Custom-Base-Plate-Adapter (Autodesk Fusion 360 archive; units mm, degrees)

design "Custom-Base-Plate-Adapter" references "Base"
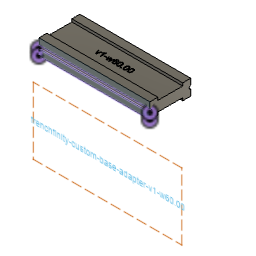
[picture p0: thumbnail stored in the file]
parameter "width" = 60
component_insert "Component Insert"
extrude "Extrude2" new body of existing geometry blind 1
extrude "Extrude1" add of existing geometry blind 59 (= "width - 1 mm")
mirror "Mirror1" mirrorStitchTolerance 0.1
sketch "Filename" plane through (0, 44.7318, 0) normal (0, -1, 0) x axis (1, 0, 0)
  line L1 (40, 50.6559) -> (40, 53.9359)
  line L2 (99, 53.9359) -> (99, 50.6559)
  line L3 (40, 53.9359) -> (99, 53.9359)
  curve K1
  curve K2
  curve K3
  curve K4
  line L4 (99, 50.6559) -> (40, 50.6559)
  line L5 (40, 45.6759) -> (40, 48.9559)
  line L6 (99, 45.6759) -> (40, 45.6759)
  line L7 (99, 48.9559) -> (99, 45.6759)
  line L8 (40, 48.9559) -> (99, 48.9559)
  dimension "d12" Text1-Height = 3
sketch "Name on piece" plane through (0, 0, 52.4859) normal (0, 0, 1) x axis (-1, 0, 0)
  dimension "d13" = 3
extrude "Extrude4" cut sketch "Name on piece" against normal blind 2

design "Base"
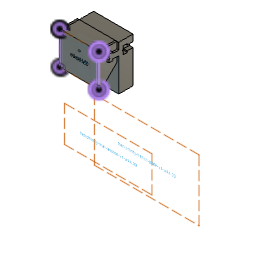
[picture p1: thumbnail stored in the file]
parameter "wall_anchor_height" = 60
parameter "wall_anchor_width" = 20
parameter "wall_anchor_angle" = 45
parameter "width_per_slot" = 40
parameter "slot_inner_width" = 8.5
parameter "slot_inner_height" = 4.5
parameter "slot_outer_width" = 5.6
parameter "slot_outer_height" = 6.5
parameter "slot_dept" = 15
parameter "print_tolerance" = 0.12
parameter "base_plate_thickness" = 16
parameter "base_plate_slot_height" = 50
parameter "wall_anchor_angle_rounded_border" = 1.5
parameter "base_plate_screw_hole_diameter" = 4
parameter "base_plate_screw_head_diameter" = 8
parameter "base_plate_screw_head_height" = 4
parameter "base_plate_screw_hole_side_distance" = 7
parameter "slot_screw_head_width" = 4.42 (= "4.3 mm + print_tolerance")
parameter "slot_screw_thread_width" = 2.12 (= "2 mm + print_tolerance")
parameter "slot_screw_head_height" = 2.12 (= "2 mm + print_tolerance")
parameter "width" = 44
parameter "filament_hole_width" = 1.7
sketch "Side" plane through (0, 0, 0) normal (1, 0, 0) x axis (0, 1, 0)
  line L1 (39.6118, 0) -> (19.6118, 0)
  line L2 (39.6118, 60) -> (39.6118, 0)
  line L3 (19.6118, 60) -> (39.6118, 60)
  line L4 (19.6118, 0) -> (19.6118, 60)
  line L5 (39.6118, 39.6118) -> (0, 0)
  line L6 (56.0196, 0) -> (0, 0)
  point P1 (0, 0)
  point P6 (0, 0)
  point P7 (39.6118, 39.6118)
  point P2 (19.6118, 0)
  point P3 (39.6118, 0)
  point P5 (19.6118, 60)
  horizontal L1
  vertical L2
  horizontal L3
  vertical L4
  horizontal L6
  coincident P1 P6
  coincident L2 P7
  dimension "d4" distance P2 P3 = 20 (= "wall_anchor_width")
  dimension "d5" distance P2 P5 = 60 (= "wall_anchor_height")
  dimension "d6" angle L5 L6 = 45 (= "wall_anchor_angle")
extrude "Extrude1" new body sketch "Side" profile of L1 L2 L3 L4 L5 along normal blind 40 (= "width_per_slot")
sketch "Slot LeftToRight" plane through (0, 0, 0) normal (-1, 0, 0) x axis (0, -1, 0)
  line L1 (-19.6118, 60) -> (-19.6118, 19.6118)
  line L2 (-39.6118, 60) -> (-19.6118, 60)
  line L3 (-39.6118, 39.6118) -> (-39.6118, 60)
  line L4 (-19.6118, 19.6118) -> (-39.6118, 39.6118)
  line L5 (-39.6118, 52.6059) -> (-39.6118, 49.8059)
  line L6 (-39.6118, 47.0059) -> (-39.6118, 49.8059)
  line L7 (-33.1118, 52.6059) -> (-39.6118, 52.6059)
  line L8 (-28.6118, 49.8059) -> (-39.6118, 49.8059)
  line L9 (-28.6118, 54.0559) -> (-28.6118, 49.8059)
  line L10 (-33.1118, 54.0559) -> (-28.6118, 54.0559)
  line L11 (-33.1118, 52.6059) -> (-33.1118, 54.0559)
  line L12 (-28.6118, 45.5559) -> (-28.6118, 49.8059)
  line L13 (-33.1118, 45.5559) -> (-28.6118, 45.5559)
  line L14 (-33.1118, 47.0059) -> (-33.1118, 45.5559)
  line L15 (-33.1118, 47.0059) -> (-39.6118, 47.0059)
  point P6 (-39.6118, 49.8059)
  point P7 (-39.6118, 52.6059)
  point P17 (-39.6118, 47.0059)
  point P9 (-33.1118, 52.6059)
  point P16 (-33.1118, 47.0059)
  point P10 (-28.6118, 49.8059)
  point P13 (-28.6118, 49.8059)
  point P11 (-28.6118, 54.0559)
  point P14 (-28.6118, 45.5559)
  point P12 (-33.1118, 54.0559)
  point P15 (-33.1118, 45.5559)
  midpoint L3 P6
  parallel L3 L5
  parallel L3 L6
  perpendicular L3 L7
  perpendicular L6 L8
  perpendicular L8 L9
  perpendicular L9 L10
  symmetric P7 L8 P17
  symmetric P9 L8 P16
  symmetric P10 L8 P13
  symmetric L8 P11 P14
  symmetric L8 P12 P15
  dimension "d80" distance P6 P7 = 2.8 (= "slot_outer_width / 2")
  dimension "d82" distance P7 P9 = 6.5 (= "slot_outer_height")
  dimension "d84" distance P6 P10 = 11 (= "slot_outer_height + slot_inner_height")
  dimension "d85" distance P10 P11 = 4.25 (= "slot_inner_width / 2")
  dimension "d86" distance P11 P12 = 4.5 (= "slot_inner_height")
extrude "Extrude3" cut sketch "Slot LeftToRight" profile of L3 L5 L6 L7 L9 L10 L11 L12 L13 L14 L15 against normal blind 40 (magnitude of "width_per_slot * -1")
sketch "Plate" plane through (0, 39.6118, 0) normal (0, 1, 0) x axis (-1, 0, 0)
  line L1 (0, 39.6118) -> (-40, 39.6118)
  line L2 (-40, 60) -> (0, 60)
  line L3 (0, 10) -> (0, 60)
  line L4 (-40, 10) -> (-40, 60)
  line L5 (-40, 10) -> (0, 10)
  line L6 (-40, 47.0059) -> (0, 47.0059)
  line L7 (-40, 52.6059) -> (-40, 60)
  line L8 (0, 60) -> (0, 52.6059)
  line L9 (0, 52.6059) -> (-40, 52.6059)
  line L10 (-40, 60) -> (0, 60)
  line L11 (-40, 39.6118) -> (-40, 47.0059)
  line L12 (0, 47.0059) -> (0, 39.6118)
  point P2 (0, 60)
  point P3 (-40, 60)
  point P4 (0, 10)
  point P5 (-40, 10)
  perpendicular L1 L3
  perpendicular L1 L4
  dimension "d36" distance P2 P3 = 40 (= "width_per_slot")
  dimension "d37" distance P2 P4 = 50 (= "base_plate_slot_height")
  dimension "d39" distance P3 P5 = 50 (= "base_plate_slot_height")
extrude "Extrude6" new body sketch "Plate" profile of L1 L2 L3 L4 L5 L6 L7 L8 L9 L10 along normal blind 16 (= "base_plate_thickness") bodies "Base plate with slot"
sketch "Slot" plane through (0, 0, 0) normal (-1, 0, 0) x axis (0, -1, 0)
  line L1 (-19.6118, 60) -> (-19.6118, 19.6118)
  line L2 (-39.6118, 60) -> (-19.6118, 60)
  line L3 (-39.6118, 52.6059) -> (-39.6118, 60)
  line L4 (-33.1118, 52.6059) -> (-39.6118, 52.6059)
  line L5 (-33.1118, 54.0559) -> (-33.1118, 52.6059)
  line L6 (-28.6118, 54.0559) -> (-33.1118, 54.0559)
  line L7 (-28.6118, 45.5559) -> (-28.6118, 54.0559)
  line L8 (-33.1118, 45.5559) -> (-28.6118, 45.5559)
  line L9 (-33.1118, 47.0059) -> (-33.1118, 45.5559)
  line L10 (-39.6118, 47.0059) -> (-33.1118, 47.0059)
  line L11 (-39.6118, 39.6118) -> (-39.6118, 47.0059)
  line L12 (-19.6118, 19.6118) -> (-39.6118, 39.6118)
  line L13 (-33.1118, 52.6059) -> (-39.6118, 52.6059)
  line L14 (-33.1118, 54.0559) -> (-33.1118, 52.6059)
  line L15 (-28.6118, 54.0559) -> (-33.1118, 54.0559)
  line L16 (-28.6118, 45.5559) -> (-28.6118, 54.0559)
  line L17 (-33.1118, 45.5559) -> (-28.6118, 45.5559)
  line L18 (-33.1118, 47.0059) -> (-33.1118, 45.5559)
  line L19 (-39.6118, 47.0059) -> (-33.1118, 47.0059)
  line L20 (-39.6118, 10) -> (-39.6118, 60)
  line L21 (-32.9918, 52.4859) -> (-39.6118, 52.4859)
  line L22 (-32.9918, 53.9359) -> (-32.9918, 52.4859)
  line L23 (-28.7318, 53.9359) -> (-32.9918, 53.9359)
  line L24 (-28.7318, 45.6759) -> (-28.7318, 53.9359)
  line L25 (-32.9918, 45.6759) -> (-28.7318, 45.6759)
  line L26 (-32.9918, 47.1259) -> (-32.9918, 45.6759)
  line L27 (-39.6118, 47.1259) -> (-32.9918, 47.1259)
  line L28 (-33.1118, 52.6059) -> (-39.6118, 52.6059)
  line L29 (-33.1118, 52.6059) -> (-33.1118, 54.0559)
  line L30 (-28.6118, 54.0559) -> (-33.1118, 54.0559)
  line L31 (-28.6118, 45.5559) -> (-28.6118, 54.0559)
  line L32 (-33.1118, 45.5559) -> (-28.6118, 45.5559)
  line L33 (-33.1118, 47.0059) -> (-33.1118, 45.5559)
  line L34 (-39.6118, 47.0059) -> (-33.1118, 47.0059)
  line L35 (-39.6118, 47.0059) -> (-39.6118, 52.6059)
  line L36 (-49.1118, 52.6059) -> (-55.6118, 52.6059)
  line L37 (-49.1118, 52.6059) -> (-49.1118, 54.0559)
  line L38 (-44.6118, 54.0559) -> (-49.1118, 54.0559)
  line L39 (-44.6118, 45.5559) -> (-44.6118, 54.0559)
  line L40 (-49.1118, 45.5559) -> (-44.6118, 45.5559)
  line L41 (-49.1118, 47.0059) -> (-49.1118, 45.5559)
  line L42 (-55.6118, 47.0059) -> (-49.1118, 47.0059)
  line L43 (-55.6118, 47.0059) -> (-55.6118, 52.6059)
  point P15 (-39.6118, 52.6059)
  point P33 (-39.6118, 52.6059)
  point P16 (-33.1118, 52.6059)
  point P34 (-33.1118, 52.6059)
  point P17 (-33.1118, 54.0559)
  point P35 (-33.1118, 54.0559)
  point P36 (-33.1118, 52.6059)
  point P18 (-28.6118, 54.0559)
  point P37 (-28.6118, 54.0559)
  point P19 (-28.6118, 45.5559)
  point P38 (-28.6118, 45.5559)
  point P10 (-28.6118, 45.5559)
  point P39 (-28.6118, 45.5559)
  point P11 (-33.1118, 45.5559)
  point P40 (-33.1118, 45.5559)
  point P41 (-33.1118, 45.5559)
  point P12 (-33.1118, 47.0059)
  point P42 (-33.1118, 47.0059)
  point P21 (-33.1118, 47.0059)
  point P43 (-33.1118, 47.0059)
  point P22 (-39.6118, 47.0059)
  point P44 (-39.6118, 47.0059)
  point P45 (-39.6118, 52.6059)
  point P46 (-39.6118, 47.0059)
  coincident P15 P33
  coincident P16 P34
  coincident P17 P35
  coincident P16 P36
  coincident P18 P37
  coincident P19 P38
  coincident P10 P39
  coincident P11 P40
  coincident P11 P41
  coincident P12 P42
  coincident P21 P43
  coincident P22 P44
  coincident P15 P45
  coincident P22 P46
  dimension "d91" = 0.12 (= "print_tolerance")
  dimension "d96" R-Pattern1-uDistance = -16 (= "base_plate_thickness * -1")
  dimension "d97" R-Pattern1-vDistance = 0
extrude "Extrude7" add sketch "Slot" profile of L20 L24 L23 L27 L22 L25 L26 L21 against normal blind 40 (magnitude of "width_per_slot * -1")
extrude "Extrude8" cut sketch "Slot" profile of L36 L37 L38 L39 L40 L41 L42 L43 no distance stored
sketch "Sketch3" plane through (0, 0, 0) normal (-1, 0, 0) x axis (0, -1, 0)
  line L1 (-32.9918, 47.1259) -> (-39.6118, 47.1259)
  line L2 (-32.9918, 45.6759) -> (-32.9918, 47.1259)
  line L3 (-28.7318, 45.6759) -> (-32.9918, 45.6759)
  line L4 (-28.7318, 53.9359) -> (-28.7318, 45.6759)
  line L5 (-32.9918, 53.9359) -> (-28.7318, 53.9359)
  line L6 (-32.9918, 52.4859) -> (-32.9918, 53.9359)
  line L7 (-39.6118, 52.4859) -> (-32.9918, 52.4859)
  line L8 (-44.6118, 45.5559) -> (-44.6118, 54.0559)
  line L9 (-32.9918, 52.4859) -> (-39.6118, 52.4859)
  line L10 (-32.9918, 53.9359) -> (-32.9918, 52.4859)
  line L11 (-28.7318, 53.9359) -> (-32.9918, 53.9359)
  line L12 (-28.7318, 45.6759) -> (-28.7318, 53.9359)
  line L13 (-32.9918, 45.6759) -> (-28.7318, 45.6759)
  line L14 (-32.9918, 47.1259) -> (-32.9918, 45.6759)
  line L15 (-39.6118, 47.1259) -> (-32.9918, 47.1259)
  line L16 (-39.6118, 47.1259) -> (-39.6118, 52.4859)
  line L17 (-55.6118, 52.4859) -> (-48.9918, 52.4859)
  line L18 (-48.9918, 52.4859) -> (-48.9918, 53.9359)
  line L19 (-48.9918, 53.9359) -> (-44.7318, 53.9359)
  line L20 (-44.7318, 45.6759) -> (-44.7318, 53.9359)
  line L21 (-48.9918, 45.6759) -> (-44.7318, 45.6759)
  line L22 (-48.9918, 47.1259) -> (-48.9918, 45.6759)
  line L23 (-55.6118, 47.1259) -> (-48.9918, 47.1259)
  line L24 (-55.6118, 47.1259) -> (-55.6118, 52.4859)
  line L25 (-55.6118, 47.0059) -> (-49.1118, 47.0059)
  line L26 (-55.6118, 10) -> (-55.6118, 47.0059)
  line L27 (-39.6118, 10) -> (-55.6118, 10)
  line L28 (-39.6118, 47.1259) -> (-39.6118, 10)
  line L29 (-39.6118, 60) -> (-39.6118, 52.4859)
  line L30 (-55.6118, 60) -> (-39.6118, 60)
  line L31 (-55.6118, 52.6059) -> (-55.6118, 60)
  line L32 (-49.1118, 52.6059) -> (-55.6118, 52.6059)
  line L33 (-49.1118, 54.0559) -> (-49.1118, 52.6059)
  line L34 (-44.6118, 54.0559) -> (-49.1118, 54.0559)
  line L35 (-49.1118, 45.5559) -> (-44.6118, 45.5559)
  line L36 (-49.1118, 47.0059) -> (-49.1118, 45.5559)
  point P9 (-39.6118, 52.4859)
  point P20 (-39.6118, 52.4859)
  point P19 (-39.6118, 47.1259)
  point P21 (-39.6118, 47.1259)
  coincident P9 P20
  coincident P19 P21
  dimension "d105" R-Pattern1-vDistance = 0
extrude "Extrude3" new body sketch "Sketch3" profile of L17 L18 L19 L20 L21 L22 L23 L24 against normal blind 40 (magnitude of "width_per_slot * -1")
sketch "Screw hole" plane through (0, 28.6118, 0) normal (0, 1, 0) x axis (-1, 0, 0)
  line L1 (0, 54.0559) -> (0, 45.5559)
  line L2 (-40, 54.0559) -> (0, 54.0559)
  line L3 (-40, 45.5559) -> (-40, 54.0559)
  line L4 (0, 45.5559) -> (-40, 45.5559)
  line L5 (0, 45.5559) -> (-40, 54.0559)
  line L6 (-40, 45.5559) -> (0, 54.0559)
  circle C1 centre (-20, 49.8059) radius 2.21
  circle C2 centre (-20, 49.8059) radius 1.06
  point P4 (-40, 54.0559)
  point P6 (-40, 54.0559)
  point P2 (0, 45.5559)
  point P7 (0, 45.5559)
  point P3 (0, 54.0559)
  point P8 (0, 54.0559)
  point P5 (-40, 45.5559)
  point P9 (-40, 45.5559)
  point P10 (-20, 49.8059)
  coincident P4 P6
  coincident P2 P7
  coincident P3 P8
  coincident P5 P9
  midpoint L5 P10
  concentric C1 C2
  dimension "d119" diameter C1 = 4.42 (= "slot_screw_head_width")
  dimension "d120" diameter C2 = 2.12 (= "slot_screw_thread_width")
extrude "Extrude4" cut sketch "Screw hole" profile of C2 against normal blind 2000
extrude "Extrude5" cut sketch "Screw hole" profile of C1 C2 no distance stored
fillet "Fillet1" radius 1.5 (= "wall_anchor_angle_rounded_border")
work_plane "WorkPlane1" sketch "Slot LeftToRight" AlongDistance -20 (= "-width_per_slot / 2")
sketch "Screw head" plane through (20, 0, 0) normal (-1, 0, 0) x axis (0, -1, 0)
  line L1 (-28.6118, 52.0159) -> (-28.6118, 47.5959)
  line L2 (-26.4918, 52.0159) -> (-26.4918, 47.5959)
  line L3 (-26.4918, 48.7459) -> (-26.4918, 50.8659)
  line L4 (-26.4918, 50.8659) -> (-28.6118, 52.0159)
  line L5 (-26.4918, 52.0159) -> (-28.6118, 52.0159)
  point P3 (-28.6118, 52.0159)
  point P8 (-28.6118, 52.0159)
  point P6 (-26.4918, 50.8659)
  point P9 (-26.4918, 50.8659)
  point P10 (-28.6118, 52.0159)
  point P5 (-26.4918, 52.0159)
  point P11 (-26.4918, 52.0159)
  coincident P3 P8
  coincident P6 P9
  coincident P3 P10
  coincident P5 P11
revolve "Revolve1" sketch "Screw head" AlongAngle 360
sketch "Plate" plane through (0, 39.6118, 0) normal (0, 1, 0) x axis (-1, 0, 0)
  line L1 (0, 39.6118) -> (-40, 39.6118)
  line L2 (-40, 60) -> (0, 60)
  line L3 (0, 10) -> (0, 60)
  line L4 (-40, 10) -> (-40, 60)
  line L5 (-40, 10) -> (0, 10)
  line L6 (-40, 47.0059) -> (0, 47.0059)
  line L7 (-40, 39.6118) -> (-40, 47.0059)
  line L8 (0, 47.0059) -> (0, 39.6118)
  line L9 (0, 52.6059) -> (-40, 52.6059)
  line L10 (-40, 60) -> (0, 60)
  line L11 (0, 60) -> (0, 52.6059)
  line L12 (-40, 52.6059) -> (-40, 60)
  point P2 (0, 60)
  point P3 (-40, 60)
  point P4 (0, 10)
  point P5 (-40, 10)
  perpendicular L1 L3
  perpendicular L1 L4
  dimension "d36_1" distance P2 P3 = 40 (= "width_per_slot")
  dimension "d37_1" distance P2 P4 = 50 (= "base_plate_slot_height")
  dimension "d39_1" distance P3 P5 = 50 (= "base_plate_slot_height")
extrude "Extrude6" new body sketch "Plate" profile of L1 L2 L3 L4 L5 L6 L7 L8 L9 L10 along normal blind 16 (= "base_plate_thickness") named "d89_1" bodies "Base plate with slot"
sketch "Slot" plane through (0, 0, 0) normal (-1, 0, 0) x axis (0, -1, 0)
  line L1 (-19.6118, 60) -> (-19.6118, 23.2332)
  line L2 (-39.6118, 60) -> (-19.6118, 60)
  line L3 (-39.6118, 52.6059) -> (-39.6118, 60)
  line L4 (-33.1118, 52.6059) -> (-39.6118, 52.6059)
  line L5 (-33.1118, 54.0559) -> (-33.1118, 52.6059)
  line L6 (-28.6118, 54.0559) -> (-33.1118, 54.0559)
  line L7 (-28.6118, 45.5559) -> (-28.6118, 54.0559)
  line L8 (-33.1118, 45.5559) -> (-28.6118, 45.5559)
  line L9 (-33.1118, 47.0059) -> (-33.1118, 45.5559)
  line L10 (-39.6118, 47.0059) -> (-33.1118, 47.0059)
  line L11 (-39.6118, 39.6118) -> (-39.6118, 47.0059)
  line L12 (-22.1725, 22.1725) -> (-39.6118, 39.6118)
  line L13 (-33.1118, 52.6059) -> (-39.6118, 52.6059)
  line L14 (-33.1118, 54.0559) -> (-33.1118, 52.6059)
  line L15 (-28.6118, 54.0559) -> (-33.1118, 54.0559)
  line L16 (-28.6118, 45.5559) -> (-28.6118, 54.0559)
  line L17 (-33.1118, 45.5559) -> (-28.6118, 45.5559)
  line L18 (-33.1118, 47.0059) -> (-33.1118, 45.5559)
  line L19 (-39.6118, 47.0059) -> (-33.1118, 47.0059)
  line L20 (-39.6118, 10) -> (-39.6118, 60)
  line L21 (-32.9918, 52.4859) -> (-39.6118, 52.4859)
  line L22 (-32.9918, 53.9359) -> (-32.9918, 52.4859)
  line L23 (-28.7318, 53.9359) -> (-32.9918, 53.9359)
  line L24 (-28.7318, 45.6759) -> (-28.7318, 53.9359)
  line L25 (-32.9918, 45.6759) -> (-28.7318, 45.6759)
  line L26 (-32.9918, 47.1259) -> (-32.9918, 45.6759)
  line L27 (-39.6118, 47.1259) -> (-32.9918, 47.1259)
  line L28 (-33.1118, 52.6059) -> (-39.6118, 52.6059)
  line L29 (-33.1118, 52.6059) -> (-33.1118, 54.0559)
  line L30 (-28.6118, 54.0559) -> (-33.1118, 54.0559)
  line L31 (-28.6118, 45.5559) -> (-28.6118, 54.0559)
  line L32 (-33.1118, 45.5559) -> (-28.6118, 45.5559)
  line L33 (-33.1118, 47.0059) -> (-33.1118, 45.5559)
  line L34 (-39.6118, 47.0059) -> (-33.1118, 47.0059)
  line L35 (-39.6118, 47.0059) -> (-39.6118, 52.6059)
  line L36 (-49.1118, 52.6059) -> (-55.6118, 52.6059)
  line L37 (-49.1118, 52.6059) -> (-49.1118, 54.0559)
  line L38 (-44.6118, 54.0559) -> (-49.1118, 54.0559)
  line L39 (-44.6118, 45.5559) -> (-44.6118, 54.0559)
  line L40 (-49.1118, 45.5559) -> (-44.6118, 45.5559)
  line L41 (-49.1118, 47.0059) -> (-49.1118, 45.5559)
  line L42 (-55.6118, 47.0059) -> (-49.1118, 47.0059)
  line L43 (-55.6118, 47.0059) -> (-55.6118, 52.6059)
  arc A1 centre (-21.1118, 23.2332) radius 1.5 clockwise from (-19.6118, 23.2332) to (-22.1725, 22.1725)
  point P15 (-39.6118, 52.6059)
  point P33 (-39.6118, 52.6059)
  point P16 (-33.1118, 52.6059)
  point P34 (-33.1118, 52.6059)
  point P17 (-33.1118, 54.0559)
  point P35 (-33.1118, 54.0559)
  point P36 (-33.1118, 52.6059)
  point P18 (-28.6118, 54.0559)
  point P37 (-28.6118, 54.0559)
  point P19 (-28.6118, 45.5559)
  point P38 (-28.6118, 45.5559)
  point P10 (-28.6118, 45.5559)
  point P39 (-28.6118, 45.5559)
  point P11 (-33.1118, 45.5559)
  point P40 (-33.1118, 45.5559)
  point P41 (-33.1118, 45.5559)
  point P12 (-33.1118, 47.0059)
  point P42 (-33.1118, 47.0059)
  point P21 (-33.1118, 47.0059)
  point P43 (-33.1118, 47.0059)
  point P22 (-39.6118, 47.0059)
  point P44 (-39.6118, 47.0059)
  point P45 (-39.6118, 52.6059)
  point P46 (-39.6118, 47.0059)
  coincident P15 P33
  coincident P16 P34
  coincident P17 P35
  coincident P16 P36
  coincident P18 P37
  coincident P19 P38
  coincident P10 P39
  coincident P11 P40
  coincident P11 P41
  coincident P12 P42
  coincident P21 P43
  coincident P22 P44
  coincident P15 P45
  coincident P22 P46
  dimension "d91_1" = 0.12 (= "print_tolerance")
  dimension "d96_1" R-Pattern1-uDistance = -16 (= "base_plate_thickness * -1")
  dimension "d97_1" R-Pattern1-vDistance = 0
extrude "Extrude8" cut sketch "Slot" profile of L36 L37 L38 L39 L40 L41 L42 L43 no distance stored
sketch "Screw" plane through (0, 55.6118, 0) normal (0, 1, 0) x axis (-1, 0, 0)
  line L1 (-40, 47.0059) -> (0, 47.0059)
  line L2 (-40, 10) -> (-40, 47.0059)
  line L3 (0, 10) -> (-40, 10)
  line L4 (0, 47.0059) -> (0, 10)
  line L5 (-33, 17) -> (-33, 40.0059)
  line L6 (-7, 17) -> (-33, 17)
  line L7 (-7, 40.0059) -> (-7, 17)
  line L8 (-33, 40.0059) -> (-7, 40.0059)
  circle C1 centre (-33, 17) radius 4
  circle C2 centre (-33, 17) radius 2
  point P7 (-33, 17)
  point P10 (-33, 17)
  coincident P7 P10
  concentric C1 C2
  dimension "d127" = -7 (= "base_plate_screw_hole_side_distance * -1")
  dimension "d128" diameter C1 = 8
  dimension "d129" diameter C2 = 4
rectangular_pattern "R-Pattern2" countU 1 (= "floor(( width / mm ) / ( width_per_slot / cm * 10 ))") uSpaceDistance 40 (= "width_per_slot") vSpaceDistance 0
work_plane "WorkPlane2"
extrude "Extrude12" new body of existing geometry no distance stored
mirror "Mirror3" mirrorStitchTolerance 0.1
sketch "filename" plane through (0, 19.6118, 0) normal (0, -1, 0) x axis (1, 0, 0)
  dimension "d216" = 3
sketch "Sketch14" plane through (0, 19.6118, 0) normal (0, -1, 0) x axis (1, 0, 0)
  line L1 (42, 60) -> (42, 23.2332)
  line L2 (40, 23.2332) -> (40, 60)
  line L3 (42, 23.2332) -> (40, 23.2332)
  line L4 (42, 60) -> (42, 23.2332)
  line L5 (40, 60) -> (42, 60)
  line L6 (0, 60) -> (0, 23.2332)
  line L7 (-2, 60) -> (0, 60)
  line L8 (-2, 23.2332) -> (-2, 60)
  line L9 (0, 23.2332) -> (-2, 23.2332)
  curve K1
  curve K2
  curve K3
  curve K4
  point P4 (42, 23.2332)
  point P2 (-2, 60)
  coincident P4
  coincident P2
  dimension "d229" Text1-Height = 3
extrude "Extrude19" cut sketch "Sketch14" against normal blind 2
extrude "Extrude14" cut of existing geometry blind 2 (= "( width_per_slot - width ) / -2")
extrude "Extrude15" cut of existing geometry blind 2 (= "( width_per_slot - width ) / -2")
extrude "Extrude9" cut of existing geometry blind -39 (= "-width_per_slot + 1 mm")
extrude "Extrude10" add of existing geometry blind 43 (= "width - 1 mm")
sketch "Sketch7" plane through (0, 39.6118, 0) normal (0, -1, 0) x axis (1, 0, 0)
  dimension "d236" = 3
extrude "Extrude11" cut sketch "Sketch7" against normal blind 2
sketch "Sketch8" plane through (0, 39.6118, 0) normal (0, -1, 0) x axis (1, 0, 0)
  line L1 (16.0624, 30.0752) -> (15.825, 30.0752)
  line L2 (16.0624, 27.063) -> (16.0624, 30.0752)
  line L3 (15.6941, 27.063) -> (16.0624, 27.063)
  line L4 (15.6941, 29.4102) -> (15.6941, 27.063)
  curve K1 (15.3441, 29.1564) -> (15.6941, 29.4102)
  curve K2 (14.9574, 28.9661) -> (15.3441, 29.1564)
  line L5 (14.9574, 29.3222) -> (14.9574, 28.9661)
  curve K3 (15.4976, 29.6741) -> (14.9574, 29.3222)
  curve K4 (15.825, 30.0752) -> (15.4976, 29.6741)
  line L6 (19.2896, 27.063) -> (19.7295, 28.7349)
  line L7 (18.9048, 27.063) -> (19.2896, 27.063)
  line L8 (18.2398, 29.2362) -> (18.9048, 27.063)
  line L9 (18.6204, 29.2362) -> (18.2398, 29.2362)
  line L10 (18.9662, 27.9818) -> (18.6204, 29.2362)
  line L11 (19.0952, 27.5152) -> (18.9662, 27.9818)
  curve K5 (19.2077, 27.9634) -> (19.0952, 27.5152)
  line L12 (19.5535, 29.2362) -> (19.2077, 27.9634)
  line L13 (19.9321, 29.2362) -> (19.5535, 29.2362)
  line L14 (20.2575, 27.9756) -> (19.9321, 29.2362)
  line L15 (20.366, 27.5602) -> (20.2575, 27.9756)
  line L16 (20.4908, 27.9797) -> (20.366, 27.5602)
  line L17 (20.8632, 29.2362) -> (20.4908, 27.9797)
  line L18 (21.2213, 29.2362) -> (20.8632, 29.2362)
  line L19 (20.5419, 27.063) -> (21.2213, 29.2362)
  line L20 (20.1593, 27.063) -> (20.5419, 27.063)
  line L21 (19.8134, 28.3645) -> (20.1593, 27.063)
  line L22 (19.7295, 28.7349) -> (19.8134, 28.3645)
  line L23 (22.9771, 27.063) -> (22.9771, 27.7812)
  line L24 (22.6088, 27.063) -> (22.9771, 27.063)
  line L25 (22.6088, 27.7812) -> (22.6088, 27.063)
  line L26 (21.3073, 27.7812) -> (22.6088, 27.7812)
  line L27 (21.3073, 28.1189) -> (21.3073, 27.7812)
  line L28 (22.6763, 30.063) -> (21.3073, 28.1189)
  line L29 (22.9771, 30.063) -> (22.6763, 30.063)
  line L30 (22.9771, 28.1189) -> (22.9771, 30.063)
  line L31 (23.3823, 28.1189) -> (22.9771, 28.1189)
  line L32 (23.3823, 27.7812) -> (23.3823, 28.1189)
  line L33 (22.9771, 27.7812) -> (23.3823, 27.7812)
  line L34 (26.7159, 27.063) -> (26.7159, 27.4825)
  line L35 (26.2964, 27.063) -> (26.7159, 27.063)
  line L36 (26.2964, 27.4825) -> (26.2964, 27.063)
  line L37 (26.7159, 27.4825) -> (26.2964, 27.4825)
  curve K6 (27.5508, 27.3228) -> (28.2323, 27.0118)
  curve K7 (27.2541, 28.5425) -> (27.5508, 27.3228)
  curve K8 (27.3626, 29.3979) -> (27.2541, 28.5425)
  curve K9 (27.6879, 29.8992) -> (27.3626, 29.3979)
  curve K10 (28.2323, 30.0752) -> (27.6879, 29.8992)
  curve K11 (28.6559, 29.977) -> (28.2323, 30.0752)
  curve K12 (28.9567, 29.6967) -> (28.6559, 29.977)
  curve K13 (29.1429, 29.2505) -> (28.9567, 29.6967)
  curve K14 (29.2104, 28.5425) -> (29.1429, 29.2505)
  curve K15 (29.102, 27.6892) -> (29.2104, 28.5425)
  curve K16 (28.7766, 27.1878) -> (29.102, 27.6892)
  curve K17 (28.2323, 27.0118) -> (28.7766, 27.1878)
  line L38 (25.308, 27.063) -> (25.308, 27.7812)
  line L39 (24.9396, 27.063) -> (25.308, 27.063)
  line L40 (24.9396, 27.7812) -> (24.9396, 27.063)
  line L41 (23.6381, 27.7812) -> (24.9396, 27.7812)
  line L42 (23.6381, 28.1189) -> (23.6381, 27.7812)
  line L43 (25.0072, 30.063) -> (23.6381, 28.1189)
  line L44 (25.308, 30.063) -> (25.0072, 30.063)
  line L45 (25.308, 28.1189) -> (25.308, 30.063)
  line L46 (25.7132, 28.1189) -> (25.308, 28.1189)
  line L47 (25.7132, 27.7812) -> (25.7132, 28.1189)
  line L48 (25.308, 27.7812) -> (25.7132, 27.7812)
  curve K18 (29.8816, 27.3228) -> (30.5631, 27.0118)
  curve K19 (29.5849, 28.5425) -> (29.8816, 27.3228)
  curve K20 (29.6934, 29.3979) -> (29.5849, 28.5425)
  curve K21 (30.0188, 29.8992) -> (29.6934, 29.3979)
  curve K22 (30.5631, 30.0752) -> (30.0188, 29.8992)
  curve K23 (30.9867, 29.977) -> (30.5631, 30.0752)
  curve K24 (31.2875, 29.6967) -> (30.9867, 29.977)
  curve K25 (31.4737, 29.2505) -> (31.2875, 29.6967)
  curve K26 (31.5413, 28.5425) -> (31.4737, 29.2505)
  curve K27 (31.4328, 27.6892) -> (31.5413, 28.5425)
  curve K28 (31.1074, 27.1878) -> (31.4328, 27.6892)
  curve K29 (30.5631, 27.0118) -> (31.1074, 27.1878)
  line L49 (18.0965, 27.9634) -> (18.0965, 28.3338)
  line L50 (16.9649, 27.9634) -> (18.0965, 27.9634)
  line L51 (16.9649, 28.3338) -> (16.9649, 27.9634)
  line L52 (18.0965, 28.3338) -> (16.9649, 28.3338)
  line L53 (13.6293, 27.063) -> (14.4519, 29.2362)
  line L54 (13.2855, 27.063) -> (13.6293, 27.063)
  line L55 (12.4587, 29.2362) -> (13.2855, 27.063)
  line L56 (12.8475, 29.2362) -> (12.4587, 29.2362)
  line L57 (13.3141, 27.9347) -> (12.8475, 29.2362)
  curve K30 (13.4533, 27.4968) -> (13.3141, 27.9347)
  curve K31 (13.5904, 27.9102) -> (13.4533, 27.4968)
  line L58 (14.0733, 29.2362) -> (13.5904, 27.9102)
  line L59 (14.4519, 29.2362) -> (14.0733, 29.2362)
  line L60 (0, 47.1259) -> (44, 47.1259)
  line L61 (0, 10) -> (0, 47.1259)
  line L62 (44, 10) -> (0, 10)
  line L63 (44, 47.1259) -> (44, 10)
  curve K32
  curve K33
  curve K34
  curve K35
  dimension "d239" Text1-Height = 3
sketch "Sketch4" plane through (40, 0, 0) normal (1, 0, 0) x axis (0, 1, 0)
  line L1 (44.7318, 53.9359) -> (48.9918, 53.9359)
  line L2 (44.7318, 45.6759) -> (44.7318, 53.9359)
  line L3 (48.9918, 45.6759) -> (44.7318, 45.6759)
  line L4 (48.9918, 47.1259) -> (48.9918, 45.6759)
  line L5 (55.6118, 47.1259) -> (48.9918, 47.1259)
  line L6 (55.6118, 52.4859) -> (55.6118, 47.1259)
  line L7 (48.9918, 52.4859) -> (55.6118, 52.4859)
  line L8 (48.9918, 53.9359) -> (48.9918, 52.4859)
  circle C1 centre (44.7318, 49.8059) radius 0.85
  point P10 (44.7318, 49.8059)
  midpoint L2 P10
  dimension "d241" diameter C1 = 1.7 (= "filament_hole_width")
extrude "Extrude4" cut sketch "Sketch4" profile of L2 C1 no distance stored
sketch "Sketch15" plane through (-2, 0, 0) normal (-1, 0, 0) x axis (0, -1, 0)
  line L1 (-19.6118, 60) -> (-19.6118, 23.2332)
  line L2 (-39.6118, 60) -> (-19.6118, 60)
  line L3 (-39.6118, 52.6059) -> (-39.6118, 60)
  line L4 (-33.1118, 52.6059) -> (-39.6118, 52.6059)
  line L5 (-33.1118, 54.0559) -> (-33.1118, 52.6059)
  line L6 (-28.6118, 54.0559) -> (-33.1118, 54.0559)
  line L7 (-28.6118, 45.5559) -> (-28.6118, 54.0559)
  line L8 (-33.1118, 45.5559) -> (-28.6118, 45.5559)
  line L9 (-33.1118, 47.0059) -> (-33.1118, 45.5559)
  line L10 (-39.6118, 47.0059) -> (-33.1118, 47.0059)
  line L11 (-39.6118, 39.6118) -> (-39.6118, 47.0059)
  line L12 (-22.1725, 22.1725) -> (-39.6118, 39.6118)
  arc A1 centre (-21.1118, 23.2332) radius 1.5 clockwise from (-19.6118, 23.2332) to (-22.1725, 22.1725)
  circle C1 centre (-28.6118, 49.8059) radius 0.85
  point P16 (-28.6118, 49.8059)
  midpoint L7 P16
  dimension "d244" diameter C1 = 1.7 (= "filament_hole_width")
extrude "Extrude20" cut sketch "Sketch15" profile of L7 C1 no distance stored
sketch "Sketch9" plane through (44, 0, 0) normal (1, 0, 0) x axis (0, 1, 0)
  line L1 (49.1118, 47.0059) -> (55.6118, 47.0059)
  line L2 (49.1118, 45.5559) -> (49.1118, 47.0059)
  line L3 (44.6118, 45.5559) -> (49.1118, 45.5559)
  line L4 (44.6118, 54.0559) -> (44.6118, 45.5559)
  line L5 (49.1118, 54.0559) -> (44.6118, 54.0559)
  line L6 (49.1118, 52.6059) -> (49.1118, 54.0559)
  line L7 (55.6118, 52.6059) -> (49.1118, 52.6059)
  line L8 (55.6118, 60) -> (55.6118, 52.6059)
  line L9 (39.6118, 60) -> (55.6118, 60)
  line L10 (39.6118, 52.4859) -> (39.6118, 60)
  line L11 (32.9918, 52.4859) -> (39.6118, 52.4859)
  line L12 (32.9918, 53.9359) -> (32.9918, 52.4859)
  line L13 (28.7318, 53.9359) -> (32.9918, 53.9359)
  line L14 (28.7318, 45.6759) -> (28.7318, 53.9359)
  line L15 (32.9918, 45.6759) -> (28.7318, 45.6759)
  line L16 (32.9918, 47.1259) -> (32.9918, 45.6759)
  line L17 (39.6118, 47.1259) -> (32.9918, 47.1259)
  line L18 (39.6118, 10) -> (39.6118, 47.1259)
  line L19 (55.6118, 10) -> (39.6118, 10)
  line L20 (55.6118, 47.0059) -> (55.6118, 10)
  circle C1 centre (28.7318, 49.8059) radius 0.85
  circle C2 centre (44.6118, 49.8059) radius 0.85
  point P22 (28.7318, 49.8059)
  point P23 (44.6118, 49.8059)
  midpoint L14 P22
  midpoint L4 P23
  dimension "d247" diameter C1 = 1.7 (= "filament_hole_width")
  dimension "d250" diameter C2 = 1.7 (= "filament_hole_width")
extrude "Extrude12" cut sketch "Sketch9" profile of L4 L14 C1 C2 no distance stored
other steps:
create_component "CreateComponent1"
create_component "CreateComponent2"
create_component "CreateComponent3"
create_component "CreateComponent4"
named bodies: "Wall anchor part", "Base plate with slot"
